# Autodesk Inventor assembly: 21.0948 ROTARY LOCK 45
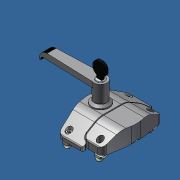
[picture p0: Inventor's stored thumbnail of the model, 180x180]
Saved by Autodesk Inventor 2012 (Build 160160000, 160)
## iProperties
Created: 2014-05
Part Number: 21.0948 ROTARY LOCK 45
Document SubType Name: Assembly
Designer: Admin
Author: Admin
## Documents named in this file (3)
- C:\Andys Backup Data\ANDY'S INVENTOR\INVENTOR LIBRARIES\PARTS LIBRARY\HANDLES LOCKS STOPS\21.0948 ROTARY LOCK 45.iam
- C:\Andys Backup Data\ANDY'S INVENTOR\INVENTOR LIBRARIES\PARTS LIBRARY\HANDLES LOCKS STOPS\SUBCOMPONENTS\21.0948 ROTARY LOCK 45 HANDLE HALF.ipt
- C:\Andys Backup Data\ANDY'S INVENTOR\INVENTOR LIBRARIES\PARTS LIBRARY\HANDLES LOCKS STOPS\SUBCOMPONENTS\21.0948 ROTARY LOCK 45 CATCH HALF.ipt
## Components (2 placed, 2 different names)
1. 21.0948 ROTARY LOCK 45 HANDLE HALF:1 — Flush:1, Flush:2, Mate:1
2. 21.0948 ROTARY LOCK 45 CATCH HALF:1 — Flush:1, Flush:2, Mate:1
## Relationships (3: Flush 2, Mate 1)
- Flush:1: 21.0948 ROTARY LOCK 45 HANDLE HALF:1 ↔ 21.0948 ROTARY LOCK 45 CATCH HALF:1
- Flush:2: 21.0948 ROTARY LOCK 45 HANDLE HALF:1 ↔ 21.0948 ROTARY LOCK 45 CATCH HALF:1
- Mate:1: 21.0948 ROTARY LOCK 45 HANDLE HALF:1 ↔ 21.0948 ROTARY LOCK 45 CATCH HALF:1
